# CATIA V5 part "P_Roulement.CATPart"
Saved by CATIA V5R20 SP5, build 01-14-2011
Part number: Roulement
Bounding box of the stored display mesh (mm): x -121.136 to 121.136, y 177.776 to 419.952, z -10 to 140
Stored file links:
  U:\2A\CFAO\dossier sans titre\P_Roulement.CATPart
  U:\2A\CFAO\dossier sans titre\Gouvernail.CATProduct
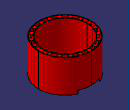
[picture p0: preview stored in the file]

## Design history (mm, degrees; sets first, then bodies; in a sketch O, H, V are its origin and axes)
External parameters (linked from other documents)
  External.Larg_Totale = 450 mm
Set1
  Point1: linked copy from another document
  Point2 "Point.23": linked copy from another document
  Point3 "Point.24": linked copy from another document
  Point4 "Point.25": linked copy from another document
Set2
  Line1: type PtPt, FirstPoint Point2, SecondPoint Point3
Body1 (main body)
  Sketch1 on xy-plane, origin (0, 0, 0), H (1, 0, 0), V (0, 1, 0)
    circle A1 centre (0, 187.7273) radius 8
    point P1 (0, 187.7273)
    axis line L1 (0, -45.0985) -> (0, 510.6121)
    point P2 (0, -45.0985)
    reference projected point E1 (0, 177.7273) from Point4
    radius A1 = 8
    distance A1 E1 = 2
    coincidence: P2 V, P1 L1
    vertical: L1 V
  Pad1 "Extrusion_rouleau": profile Sketch1, direction (0, 0, 1), length 140, opposite side length 10
  CircPattern1: of the body so far, instances 20, angular step 18, axis from Line1
  Sketch2 on xy-plane, origin (0, 0, 0), H (1, 0, 0), V (0, 1, 0)
    circle A1 centre (0, 298.8638) radius 121.1365
    point P1 (0, 298.8638)
    reference projected point E1 (0, 298.8638) from Point3
    reference projected point E2 (0, 177.7273) from Point4
    circle A2 centre (0, 298.8638) radius 119.1365
    point P2 (0, 298.8638)
    reference projected point E3 (0, 298.8638) from Point3
    distance A2 A1 = 2
    coincidence: P1 E1, A1 E2, P2 E3
  Pad2 "Extrusion_bague_ext": profile Sketch2, direction (0, 0, 1), length 140, opposite side length 10
  Sketch3 on xy-plane, origin (0, 0, 0), H (1, 0, 0), V (0, 1, 0)
    circle A1 centre (0, 298.8638) radius 103.1365
    point P1 (0, 298.8638)
    reference projected point E1 (0, 298.8638) from Point2
    circle A2 centre (0, 298.8638) radius 101.1365
    point P2 (0, 298.8638)
    reference projected point E2 (0, 298.8638) from Point2
    reference projected point E3 (0, 177.7273) from Point4
    distance A2 A1 = 2
    distance A1 E3 = 18
    coincidence: P1 E1, P2 E2
  Pad3 "Extrusion_bague_int": profile Sketch3, direction (0, 0, 1), length 140, opposite side length 10
  Sketch4 on xy-plane, origin (0, 0, 0), H (1, 0, 0), V (0, 1, 0)
    line L1 (-50, 500) -> (50, 500)
    line L2 (50, 500) -> (50, 100)
    line L3 (50, 100) -> (-50, 100)
    line L4 (-50, 100) -> (-50, 500)
    length L2 = 400 {= (400/450)*External.Larg_Totale}
    length L3 = 100 {= (100/450)*External.Larg_Totale}
    distance L3 H = 100 {= Sketch4.length(L3)}
    distance V L2 = 50 {= Sketch4.length(L3) /2}
    horizontal: L1 H, L3 H
    vertical: L2 V, L4 V
  Pocket1: profile Sketch4, direction (0, 0, -1), length 10, opposite side length 5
